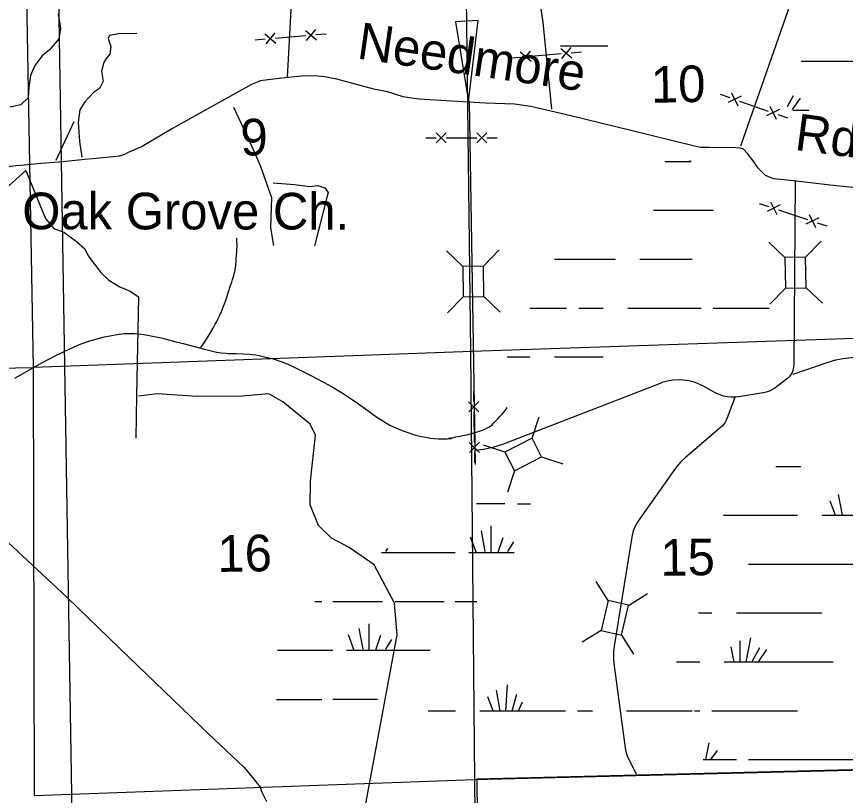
# Model space of a CAD drawing. Extents: x 2480962 to 2688785, y 277103 to 599240.
# Drawn here: x 2558984 to 2569158, y 512805 to 522366 of the extents above; entities that cross this region are included whole.
import ezdxf

# ---------------------------------------------------------------- set-up
doc = ezdxf.new("R2010")
doc.units = 0
for name, color, linetype in [('Culture Text', 7, 'Continuous'), ('Divided_Highway', 7, 'Continuous'), ('Local Roads Improved', 7, 'Continuous'), ('Local Roads Related Text', 7, 'Continuous'), ('Narrow River Creek and Branch and Slough', 7, 'Continuous'), ('National Forest', 7, 'Continuous'), ('Section Lines', 7, 'Continuous'), ('Section Numbers', 7, 'Continuous'), ('Swamps', 7, 'Continuous'), ('Uninventoried Roads and Features', 7, 'Continuous')]:
    doc.layers.add(name, color=color, linetype=linetype)

msp = doc.modelspace()

# ---------------------------------------------------------------- linework, layer by layer
at = {"layer": 'Divided_Highway'}
msp.add_line((2559790.472, 504995.814), (2559042.308, 550450.169), dxfattribs=at)
at = {"layer": 'Local Roads Improved'}
for points in [[(2569682.554, 520222.318), (2568969.841, 520298.044), (2568522.169, 520349.27), (2568277.174, 520375.997), (2568234.857, 520391.587), (2568174.721, 520416.087), (2568156.904, 520436.132), (2568087.86, 520507.403), (2568025.497, 520596.492), (2567954.226, 520685.581), (2567905.227, 520736.808), (2567865.137, 520752.398), (2567811.683, 520754.625), (2567486.508, 520759.08), (2567379.601, 520759.08), (2567303.876, 520774.67), (2566506.529, 520970.666), (2565787.134, 521148.845), (2565297.144, 521262.433), (2565094.467, 521291.387), (2564738.11, 521304.75), (2564323.846, 521327.023), (2563927.4, 521351.522), (2563858.356, 521360.431), (2563729.177, 521382.703), (2563535.408, 521440.611), (2563368.366, 521474.02), (2563112.235, 521543.064), (2562914.012, 521596.517), (2562762.56, 521625.471), (2562680.153, 521634.38), (2562593.291, 521638.834), (2562481.93, 521634.38), (2562239.162, 521609.881), (2561974.122, 521576.472), (2561927.35, 521556.427), (2561867.215, 521531.928), (2561350.499, 521244.615), (2560898.371, 520990.711), (2560524.197, 520770.216), (2560352.701, 520698.945), (2560310.384, 520674.445), (2560243.567, 520654.4), (2560167.841, 520643.264), (2559920.619, 520618.765), (2559817.758, 520611.041)], [(2559820.946, 520611.28), (2559505.445, 520581.147), (2559281.241, 520562.267), (2559079.851, 520541.813), (2558977.583, 520535.519), (2558908.355, 520527.653), (2558779.339, 520494.612), (2558661.337, 520439.544), (2557997.378, 520066.658), (2557902.976, 520010.017), (2557854.202, 519973.829), (2557824.308, 519937.642), (2557811.721, 519920.335)], [(2557703.159, 519302.004), (2557788.121, 517989.82), (2557829.028, 517417.116), (2557838.468, 517244.046), (2557854.202, 517118.177), (2557879.376, 517004.895), (2557895.109, 516935.667), (2557961.191, 516812.945), (2557992.658, 516778.331), (2558876.887, 515912.982), (2559606.927, 515233.289), (2560248.859, 514613.385), (2561340.772, 513559.232), (2561775.02, 513153.305), (2561878.862, 513024.289), (2561973.264, 512904.714), (2561992.144, 512851.219), (2562051.932, 512731.644)]]:
    msp.add_lwpolyline(points, dxfattribs=at)
at = {"layer": 'Local Roads Related Text'}
msp.add_lwpolyline([(2564529.53, 521324.883), (2564650.554, 522317.121), (2564373.394, 522300.323)], close=True, dxfattribs=at)
at = {"layer": 'Narrow River Creek and Branch and Slough'}
for points in [[(2559492.602, 522399.869), (2559521.219, 522225.841), (2559501.757, 522093.412), (2559387.202, 521959.619), (2559298.326, 521884.339), (2559209.984, 521766.78), (2559153.408, 521644.39), (2559134.213, 521490.821), (2559125.182, 521369.113), (2559036.441, 521283.264), (2558904.7, 521254.944)], [(2561245.859, 518302.248), (2561285.611, 518360.919), (2561314.376, 518405.43), (2561355.997, 518473.101), (2561395.99, 518541.969), (2561422.306, 518589.05), (2561441.514, 518624.565), (2561455.468, 518651.411), (2561475.438, 518692.162), (2561484.902, 518712.81), (2561493.963, 518733.671), (2561511.773, 518777.121), (2561524.564, 518809.88), (2561542.933, 518859.299), (2561560.439, 518909.062), (2561586.259, 518985.944), (2561611.331, 519063.086), (2561625.078, 519106.524), (2561635.03, 519139.166), (2561649.139, 519188.418), (2561655.731, 519213.245), (2561661.957, 519238.251), (2561666, 519256.592), (2561669.006, 519272.701), (2561673.255, 519301.009), (2561675.763, 519322.322), (2561678.752, 519354.389), (2561681.219, 519386.535), (2561684.933, 519438.103), (2561687.338, 519476.786), (2561688.714, 519505.798), (2561689.76, 519549.309), (2561689.703, 519571.059), (2561689.182, 519592.804), (2561688.612, 519606.278), (2561687.504, 519626.487), (2561686.254, 519646.696)], [(2558962.626, 517925.575), (2559083.253, 517996.043), (2559193.211, 518058.767), (2559303.602, 518120.782), (2559386.069, 518165.511), (2559448.553, 518197.604), (2559543.382, 518244.096), (2559639.64, 518289.47), (2559711.898, 518321.4), (2559775.885, 518346.966), (2559832.42, 518367.551), (2559882.28, 518384.217), (2559926.189, 518397.785), (2560003.623, 518419.286), (2560062.155, 518433.57), (2560106.289, 518443.265), (2560172.837, 518456.197), (2560239.759, 518467.233), (2560274.574, 518471.779), (2560305.207, 518474.648), (2560359.042, 518477.19), (2560399.47, 518477.029), (2560429.746, 518475.748), (2560474.969, 518471.97), (2560519.823, 518465.966), (2560595.67, 518453.492), (2560652.471, 518443.419), (2560737.381, 518426.561), (2560779.648, 518417.121), (2560821.752, 518406.865), (2560925.177, 518379.316), (2561028.521, 518351.687), (2561288.942, 518281.91), (2561354.368, 518266.105), (2561403.656, 518255.446), (2561440.777, 518248.296), (2561496.751, 518239.19), (2561553.135, 518232.35), (2561584.817, 518230.288), (2561632.408, 518229.619), (2561679.993, 518228.884), (2561764.602, 518225.408), (2561849.181, 518220.74), (2561875.996, 518218.372), (2561922.605, 518211.913), (2561957.353, 518205.504), (2562009.255, 518194.108), (2562061.032, 518181.491), (2562117.847, 518166.842), (2562160.057, 518154.941), (2562191.441, 518145.258), (2562238.002, 518129.15), (2562283.851, 518110.684), (2562364.862, 518074.29), (2562424.924, 518045.991), (2562514.189, 518002.098), (2562602.831, 517956.681), (2562742.054, 517883.644), (2562811.091, 517846.155), (2562879.481, 517807.356), (2562929.597, 517777.642), (2563003.756, 517731.543), (2563076.552, 517683.32), (2563180.764, 517611.155), (2563284.457, 517538.295), (2563345.791, 517494.284), (2563407.1, 517450.193), (2563445.818, 517423.844), (2563505.489, 517386.835), (2563566.857, 517352.051), (2563593.125, 517338.217), (2563639.796, 517315.957), (2563675.356, 517300.669), (2563729.538, 517279.545), (2563784.659, 517260.028), (2563842.223, 517241.551), (2563885.583, 517229.172), (2563951.214, 517213.048), (2563984.404, 517206.112), (2564017.91, 517199.943), (2564068.1, 517192.146), (2564105.764, 517187.522), (2564162.308, 517182.943), (2564190.608, 517181.863), (2564218.929, 517181.683), (2564269.847, 517183.565), (2564320.773, 517186.981)], [(2564322.2, 517186.445), (2564321.842, 517186.42), (2564321.164, 517186.34), (2564320.567, 517186.241), (2564319.523, 517186.032), (2564318.747, 517185.867), (2564318.173, 517185.751), (2564317.75, 517185.673), (2564317.127, 517185.58), (2564316.823, 517185.547), (2564316.524, 517185.525), (2564303.347, 517184.9), (2564294.362, 517184.682), (2564289.024, 517184.833), (2564286.848, 517185.317), (2564287.4, 517186.103), (2564290.296, 517187.16), (2564295.193, 517188.461), (2564301.788, 517189.981), (2564309.812, 517191.696), (2564319.026, 517193.584), (2564329.221, 517195.626), (2564352.22, 517200.176), (2564377.238, 517205.147), (2564403.291, 517210.426), (2564429.638, 517215.917), (2564455.729, 517221.537), (2564507.322, 517233.304), (2564554.154, 517244.906), (2564636.178, 517268.115), (2564665.89, 517277.764), (2564691.001, 517286.627), (2564732.247, 517303.077), (2564760.316, 517316.195), (2564779.41, 517326.47), (2564792.485, 517334.42), (2564809.877, 517346.737), (2564824.332, 517359.521), (2564847.999, 517383.412), (2564890.025, 517426.496), (2564921.267, 517460.029), (2564944.104, 517485.954), (2564960.713, 517505.869), (2564984.512, 517536.557), (2565006.631, 517568.291)]]:
    msp.add_lwpolyline(points, dxfattribs=at)
at = {"layer": 'National Forest'}
for p, q in [((2599077.417, 513844.57), (2564631.794, 513006.26)), ((2564631.794, 513006.26), (2565361.705, 460060.464))]:
    msp.add_line(p, q, dxfattribs=at)
at = {"layer": 'Section Lines'}
for p, q in [((2564491.758, 523540.193), (2564556.382, 518255.894)), ((2559193.211, 518058.767), (2559094.435, 523461.602)), ((2569803.476, 518432.474), (2564569.952, 518256.371)), ((2564569.952, 518256.371), (2559193.211, 518058.767)), ((2564556.382, 518255.894), (2564604.458, 513002.287)), ((2553915.727, 517960.418), (2559193.211, 518058.767)), ((2559202.149, 512804.954), (2559193.211, 518058.767)), ((2564604.458, 513002.287), (2575180.081, 513260.41)), ((2559202.149, 512804.954), (2564604.458, 513002.287)), ((2564604.458, 513002.287), (2564738.747, 502336.313))]:
    msp.add_line(p, q, dxfattribs=at)
at = {"layer": 'Swamps'}
for p, q in [((2567085.166, 519988.542), (2567535.166, 519988.549)), ((2565585.175, 519388.521), (2566335.174, 519388.533)), ((2566635.174, 519388.537), (2567085.174, 519388.544)), ((2565885.182, 518788.528), (2566185.182, 518788.532)), ((2566485.182, 518788.537), (2567085.181, 518788.546)), ((2567085.181, 518788.546), (2567385.181, 518788.55)), ((2565585.19, 518188.525), (2566185.19, 518188.534)), ((2569035.101, 516244.78), (2568969.628, 516416.644)), ((2569120.175, 516244.692), (2569073.92, 516499.072)), ((2564627.86, 516386.833), (2564975.641, 516386.839)), ((2564805.981, 516113.058), (2564805.985, 515786.838)), ((2564685.158, 516052.645), (2564733.491, 515798.919)), ((2564552.254, 515980.149), (2564624.751, 515786.835)), ((2564950.969, 515968.074), (2564890.561, 515786.839)), ((2565083.875, 515919.747), (2565011.383, 515798.923)), ((2563634.669, 515786.82), (2564365.524, 515786.831)), ((2567969.674, 515644.594), (2569469.673, 515644.617)), ((2562866.43, 515186.81), (2563475.658, 515186.82)), ((2563631.514, 515184.204), (2564231.513, 515184.213)), ((2567819.682, 515044.594), (2568869.681, 515044.61)), ((2563305.997, 514913.039), (2563306.002, 514586.819)), ((2563185.175, 514852.626), (2563233.507, 514598.9)), ((2563052.271, 514780.13), (2563124.768, 514586.816)), ((2563450.986, 514768.055), (2563390.577, 514586.82)), ((2563583.892, 514719.728), (2563511.4, 514598.904)), ((2567860.632, 514703.158), (2567860.636, 514444.597)), ((2567993.537, 514739.406), (2567934.6, 514444.703)), ((2563034.685, 514586.815), (2563634.684, 514586.824)), ((2567751.892, 514630.662), (2567789.104, 514444.618)), ((2568102.278, 514618.586), (2568008.272, 514443.999)), ((2568186.854, 514594.422), (2568087.536, 514445.442)), ((2564920.209, 513844.636), (2564873.954, 514099.016)), ((2564991.209, 513844.587), (2565008.445, 514160.66)), ((2564835.135, 513844.723), (2564769.662, 514016.588)), ((2565067.895, 513844.766), (2565126.128, 514048.585)), ((2565144.491, 513844.689), (2565193.375, 513953.322)), ((2564669.701, 513844.55), (2565719.699, 513844.566)), ((2565869.699, 513844.568), (2566054.273, 513844.571)), ((2566469.699, 513844.577), (2567069.698, 513844.587)), ((2567519.698, 513844.593), (2568569.696, 513844.609)), ((2567442.968, 513244.404), (2567485.853, 513450.255)), ((2567505.164, 513244.097), (2567588.942, 513357.798)), ((2567969.705, 513244.602), (2569469.703, 513244.625))]:
    msp.add_line(p, q, dxfattribs=at)
for points in [[(2565659.336, 522008.84), (2566239.835, 522008.849)], [(2568614.838, 521818.336), (2569282.838, 521818.346)], [(2568514.594, 521391.523), (2568444.095, 521257.928)], [(2568600.094, 521365.555), (2568503.596, 521224.523)], [(2568510.846, 521217.087), (2568708.874, 521217.09)], [(2566942.479, 520588.538), (2567085.159, 520588.54)], [(2567085.159, 520588.54), (2567262.25, 520588.543)], [(2567250.839, 520589.53), (2567247.714, 520597.699)], [(2566799.823, 519988.538), (2567085.166, 519988.542)], [(2567085.174, 519388.544), (2567275.875, 519388.547)], [(2565282.899, 518788.519), (2565735.183, 518788.526)], [(2567535.181, 518788.553), (2568221.582, 518788.563)], [(2565007.634, 518188.516), (2565285.191, 518188.521)], [(2568301.544, 516844.596), (2568611.492, 516844.6)], [(2565131.497, 516384.223), (2565293.978, 516384.225)], [(2567659.406, 516244.588), (2568569.666, 516244.602)], [(2568869.666, 516244.606), (2569879.901, 516244.622)], [(2563534.853, 515838.014), (2563511.385, 515798.9)], [(2563464.244, 515786.818), (2563634.669, 515786.82)], [(2564534.668, 515786.834), (2565089.546, 515786.842)], [(2562644.096, 515184.189), (2562731.514, 515184.19)], [(2564366.429, 515186.833), (2564631.527, 515186.837)], [(2567354.545, 515044.587), (2567519.682, 515044.59)], [(2562184.847, 514586.802), (2562865.541, 514586.812)], [(2563634.684, 514586.824), (2564061.572, 514586.83)], [(2567083.611, 514444.585), (2567369.69, 514444.589)], [(2567669.69, 514444.594), (2569007.563, 514444.614)], [(2562173.865, 513984.185), (2562731.53, 513984.194)], [(2562866.446, 513986.814), (2563415.345, 513986.822)], [(2564034.1, 513844.54), (2564369.701, 513844.545)], [(2567069.698, 513844.587), (2567275.731, 513844.59)], [(2567303.729, 513844.59), (2567369.698, 513844.591)], [(2567409.608, 513244.594), (2567819.705, 513244.6)]]:
    msp.add_lwpolyline(points, dxfattribs=at)
at = {"layer": 'Uninventoried Roads and Features'}
for p, q in [((2562307.358, 521623.912), (2562623.918, 527393.678)), ((2568735.115, 523260.162), (2567869.048, 520774.988)), ((2565553.217, 521230.712), (2565448.002, 522296.34)), ((2562031.049, 522154.687), (2562166.16, 522040.691)), ((2562155.602, 522165.245), (2562041.606, 522030.134)), ((2562160.881, 522102.968), (2562534.542, 522134.639)), ((2562529.263, 522196.916), (2562664.374, 522082.919)), ((2562653.817, 522207.473), (2562539.82, 522072.362)), ((2562659.096, 522145.196), (2562783.649, 522155.753)), ((2561911.774, 522081.853), (2562036.327, 522092.411)), ((2565164.268, 521932.258), (2565299.379, 521818.262)), ((2565288.821, 521942.816), (2565174.825, 521807.705)), ((2565294.1, 521880.539), (2565667.761, 521912.21)), ((2565662.482, 521974.487), (2565797.593, 521860.49)), ((2565787.036, 521985.044), (2565673.039, 521849.933)), ((2565792.315, 521922.767), (2565916.868, 521933.324)), ((2565044.993, 521859.424), (2565169.546, 521869.982)), ((2567620.926, 521412.412), (2567738.938, 521371.203)), ((2567759.543, 521430.209), (2567836.346, 521270.988)), ((2564618.799, 516865.998), (2564542.475, 521326.987)), ((2567877.555, 521389.001), (2567718.334, 521312.197)), ((2567856.951, 521329.994), (2568210.987, 521206.368)), ((2568349.604, 521224.165), (2568190.383, 521147.362)), ((2568231.592, 521265.374), (2568308.395, 521106.153)), ((2568329, 521165.159), (2568447.012, 521123.95)), ((2559685.393, 521073.433), (2559467.055, 520599.65)), ((2564132.794, 520940.929), (2564257.796, 520815.931)), ((2564257.794, 520940.931), (2564132.796, 520815.929)), ((2564632.794, 520940.936), (2564757.796, 520815.938)), ((2564757.795, 520940.938), (2564632.796, 520815.936)), ((2564007.795, 520878.428), (2564132.795, 520878.429)), ((2564257.795, 520878.431), (2564632.795, 520878.436)), ((2564757.795, 520878.438), (2564882.795, 520878.44)), ((2568541.879, 520350.275), (2568522.68, 518086.406)), ((2568236.492, 520092.854), (2568315.551, 519934.741)), ((2568098.143, 520073.088), (2568216.729, 520033.561)), ((2568355.079, 520053.327), (2568196.965, 519974.268)), ((2568335.315, 519994.034), (2568691.074, 519875.452)), ((2568829.423, 519895.218), (2568671.31, 519816.159)), ((2568710.837, 519934.745), (2568789.896, 519776.632)), ((2568809.66, 519835.925), (2568928.246, 519796.398)), ((2568413.525, 519407.752), (2568215.533, 519598.539)), ((2568669.481, 519412.495), (2568860.268, 519610.487)), ((2564459.433, 519300.187), (2564261.994, 519491.546)), ((2564715.402, 519304.19), (2564906.762, 519501.629)), ((2568669.481, 519412.495), (2568413.525, 519407.752)), ((2568413.525, 519407.752), (2568420.473, 519032.817)), ((2568676.429, 519037.56), (2568669.481, 519412.495)), ((2564715.403, 519304.19), (2564459.434, 519300.187)), ((2564459.434, 519300.187), (2564465.297, 518925.232)), ((2564721.266, 518929.235), (2564715.403, 519304.19)), ((2568421.79, 519034.183), (2568231.003, 518836.191)), ((2568420.473, 519032.817), (2568676.429, 519037.56)), ((2568676.429, 519037.56), (2568874.421, 518846.773)), ((2564466.618, 518926.595), (2564275.259, 518729.155)), ((2564465.297, 518925.232), (2564721.266, 518929.235)), ((2564721.266, 518929.235), (2564918.706, 518737.876)), ((2569608.08, 518226.534), (2569131.41, 518165.915)), ((2568940.579, 518120.719), (2568513.728, 517970.395)), ((2566884.587, 517863.349), (2564948.227, 517113.231)), ((2568435.597, 517914.556), (2568289.64, 517805.603)), ((2564592.064, 517764.18), (2564594.05, 517639.196)), ((2567559.689, 517748.865), (2567422.527, 517825.56)), ((2568148.799, 517746.035), (2567847.904, 517697.782)), ((2564658.528, 517515.204), (2564531.558, 517638.203)), ((2564656.542, 517640.189), (2564533.544, 517513.218)), ((2567799.338, 517689.372), (2567707.466, 517439.154)), ((2564596.036, 517514.211), (2564601.994, 517139.258)), ((2565311.649, 517189.143), (2565396.471, 517450.688)), ((2567624.29, 517319.736), (2567189.566, 516949.151)), ((2564666.472, 517015.267), (2564539.502, 517138.265)), ((2564664.486, 517140.251), (2564541.488, 517013.281)), ((2565311.649, 517189.143), (2564977.616, 517018.712)), ((2565427.996, 516961.11), (2565311.649, 517189.143)), ((2564714.374, 517052.191), (2564615.776, 517038.189)), ((2564977.616, 517018.712), (2564716.071, 517103.534)), ((2564603.98, 517014.274), (2564605.966, 516889.289)), ((2564977.616, 517018.712), (2565093.963, 516790.679)), ((2565093.963, 516790.679), (2565427.996, 516961.11)), ((2565426.191, 516961.695), (2565687.736, 516876.873)), ((2567073.166, 516821.731), (2566609.525, 516166.18)), ((2565093.963, 516790.679), (2565009.141, 516529.134)), ((2566541.33, 515999.826), (2566318.251, 514639.131)), ((2566245.124, 515196.729), (2566099.395, 515429.888)), ((2566245.124, 515196.729), (2566160.807, 514831.331)), ((2566494.569, 515139.169), (2566245.124, 515196.729)), ((2566492.96, 515138.163), (2566726.119, 515283.892)), ((2566410.252, 514773.771), (2566494.569, 515139.169)), ((2566160.807, 514831.331), (2565927.648, 514685.602)), ((2566160.807, 514831.331), (2566410.252, 514773.771)), ((2566410.252, 514773.771), (2566555.981, 514540.612)), ((2566315.123, 514425.511), (2566454.194, 513387.858)), ((2566493.751, 513257.341), (2566587.738, 513065.392))]:
    msp.add_line(p, q, dxfattribs=at)
for points in [[(2565448.002, 522296.34), (2565419.252, 522485.573), (2565415.2, 522504.729)], [(2560460.044, 522159.513), (2560230.803, 522152.671), (2560125.237, 522133.036), (2560108.752, 522096.003), (2560141.878, 521998.258), (2560130.553, 521905.352), (2560085.572, 521850.336), (2560053.943, 521801.397), (2560025.548, 521696.542), (2560047.743, 521571.537), (2560001.601, 521483.677), (2559927.539, 521435.759), (2559820.326, 521321.494), (2559760.967, 521221.769), (2559741.405, 521068.842), (2559754.653, 520831.677), (2559784.161, 520641.191)], [(2561645.482, 521256.345), (2561836.104, 520853.097), (2561976.619, 520531.787), (2562048.787, 520330.632), (2562112.886, 520144.75), (2562100.387, 519771.9), (2562138.233, 519554.566)], [(2557911.796, 519658.522), (2558223.405, 519690.616), (2559095.901, 520476.448), (2559270.993, 520056.865), (2559339.538, 519886.307), (2559441.903, 519764.526), (2559564.126, 519718.296), (2559718.334, 519607.006), (2559820.186, 519514.151), (2559864.073, 519429.993)], [(2562131.818, 520324.689), (2562396.416, 520303.33), (2562582.017, 520280.279), (2562681.938, 520294.003), (2562767.437, 520264.946), (2562809.296, 520205.998), (2562791.425, 520145.771), (2562639.508, 519551.79)], [(2559864.073, 519429.993), (2560017.703, 519225.362), (2560114.412, 519128.979), (2560249.296, 519048.858), (2560379.741, 518993.738), (2560479.673, 518924.451), (2560453.926, 517715.42), (2560446.867, 517192.108)], [(2569131.41, 518165.915), (2569036.001, 518148.666), (2568942.917, 518121.539), (2568940.579, 518120.719)], [(2568522.68, 518086.406), (2568521.3, 518063.761), (2568517.562, 518041.385), (2568511.504, 518019.521), (2568503.195, 517998.411), (2568492.724, 517978.285), (2568480.207, 517959.364), (2568465.781, 517941.855), (2568449.603, 517925.948), (2568435.597, 517914.556)], [(2567422.527, 517825.56), (2567363.045, 517854.845), (2567300.828, 517877.752), (2567236.556, 517894.029), (2567170.936, 517903.499), (2567104.684, 517906.058), (2567038.528, 517901.678), (2566973.193, 517890.407), (2566909.393, 517872.368), (2566884.587, 517863.349)], [(2562110.47, 510835.93), (2562847.522, 510890.328), (2562895.555, 510897.149), (2562956.571, 511008.494), (2563656.996, 514778.278), (2563621.011, 515163.602), (2563372.845, 515637.045), (2563067.134, 515850.571), (2562848.632, 515961.719), (2562690.797, 516116.638), (2562586.495, 516373.087), (2562593.225, 516662.803), (2562630.683, 517040.049), (2562653.332, 517225.86), (2562586.551, 517361.493), (2562250.45, 517638.074), (2562078.507, 517736.707), (2561751.497, 517706.536), (2561202.232, 517700.561), (2560707.898, 517736.304), (2560481.126, 517706.349)], [(2567847.904, 517697.782), (2567801.498, 517692.814), (2567754.826, 517692.724), (2567708.4, 517697.513), (2567662.73, 517707.128), (2567618.314, 517721.464), (2567575.641, 517740.366), (2567559.689, 517748.865)], [(2568289.64, 517805.603), (2568261.768, 517786.987), (2568232.104, 517771.387), (2568200.971, 517758.972), (2568168.712, 517749.88), (2568148.799, 517746.035)], [(2567707.466, 517439.154), (2567695.657, 517411.552), (2567681.028, 517385.334), (2567663.738, 517360.789), (2567643.977, 517338.187), (2567624.29, 517319.736)], [(2564948.227, 517113.231), (2564842.818, 517078.624), (2564734.37, 517055.225), (2564714.374, 517052.191)], [(2567189.566, 516949.151), (2567136.82, 516899.192), (2567089.586, 516843.992), (2567073.166, 516821.731)], [(2566609.525, 516166.18), (2566587.158, 516130.758), (2566568.616, 516093.192), (2566554.102, 516053.893), (2566543.776, 516013.293), (2566541.33, 515999.826)], [(2566318.251, 514639.131), (2566309.909, 514563.697), (2566309.497, 514487.803), (2566315.123, 514425.511)], [(2566454.194, 513387.858), (2566462.408, 513344.111), (2566475.149, 513301.462), (2566492.278, 513260.38), (2566493.751, 513257.341)]]:
    msp.add_lwpolyline(points, dxfattribs=at)

# ---------------------------------------------------------------- texts
at = {"layer": 'Culture Text'}
msp.add_text('Oak Grove Ch.', height=450, rotation=359.9501722, dxfattribs=at).set_placement((2559053.463, 519755.341))
at = {"layer": 'Local Roads Related Text'}
for s, rotation, p in [('Needmore', 351.6952083, (2563150.633, 521852.903)), ('Rd.', 352.5490472, (2568523.807, 520731.126))]:
    msp.add_text(s, height=450, rotation=rotation, dxfattribs=at).set_placement(p)
at = {"layer": 'Section Numbers'}
for s, rotation, p in [('10', 0.8220333, (2566772.856, 521308.596)), ('9', 0.8220361, (2561735.059, 520659.62)), ('16', 0.8220444, (2561451.628, 515548.143)), ('15', 0.8220444, (2566888.913, 515499.92))]:
    msp.add_text(s, height=450, rotation=rotation, dxfattribs=at).set_placement(p)

doc.saveas('drawing.dxf')
